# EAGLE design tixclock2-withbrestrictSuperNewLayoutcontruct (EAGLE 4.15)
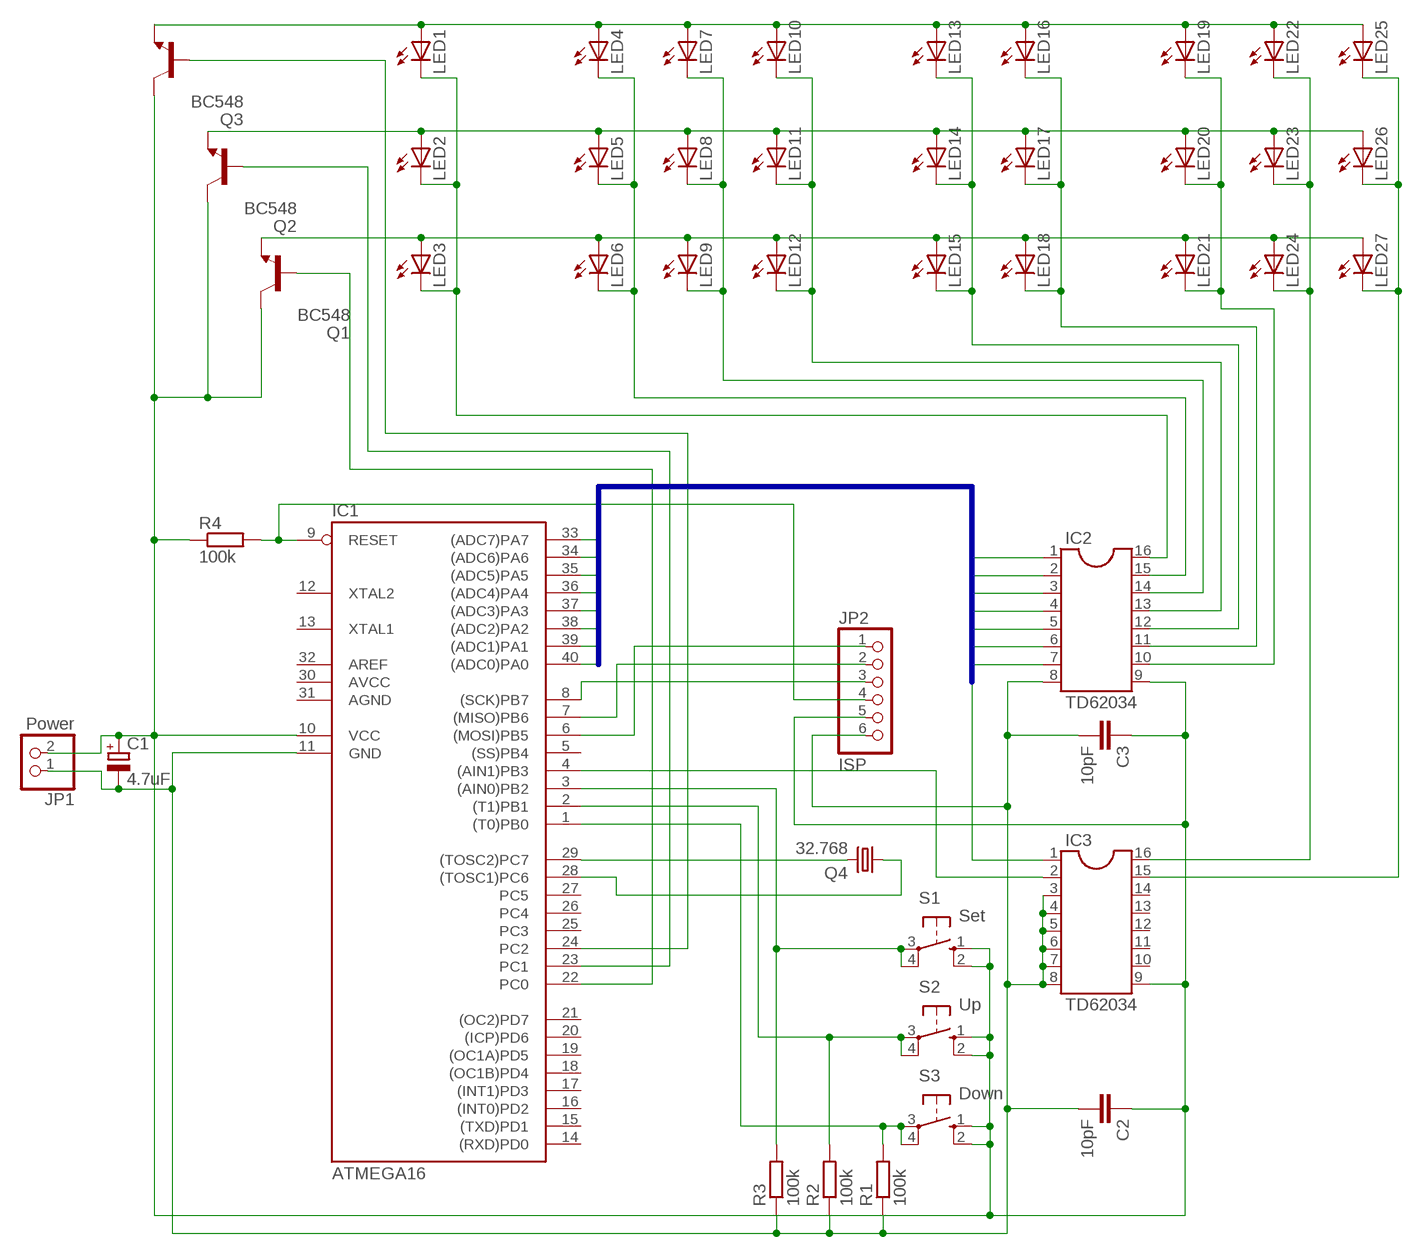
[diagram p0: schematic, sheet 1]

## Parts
C1  4.7uF  CPOL-EUE2.5-6  [E2,5-6]
C2  10pF  C-EU050-024X044  [C050-024X044]
C3  10pF  C-EU050-024X044  [C050-024X044]
IC1  ATMEGA16  AT90S8535P  [DIL40]
IC2  TD62034  DIL16  [DIL16]
IC3  TD62034  DIL16  [DIL16]
JP1  Power  PINHD-1X2  [1X02]
JP2  ISP  PINHD-1X6  [1X06]
LED1  LED5MM  [LED5MM]
LED2  LED5MM  [LED5MM]
LED3  LED5MM  [LED5MM]
LED4  LED5MM  [LED5MM]
LED5  LED5MM  [LED5MM]
LED6  LED5MM  [LED5MM]
LED7  LED5MM  [LED5MM]
LED8  LED5MM  [LED5MM]
LED9  LED5MM  [LED5MM]
LED10  LED5MM  [LED5MM]
LED11  LED5MM  [LED5MM]
LED12  LED5MM  [LED5MM]
LED13  LED5MM  [LED5MM]
LED14  LED5MM  [LED5MM]
LED15  LED5MM  [LED5MM]
LED16  LED5MM  [LED5MM]
LED17  LED5MM  [LED5MM]
LED18  LED5MM  [LED5MM]
LED19  LED5MM  [LED5MM]
LED20  LED5MM  [LED5MM]
LED21  LED5MM  [LED5MM]
LED22  LED5MM  [LED5MM]
LED23  LED5MM  [LED5MM]
LED24  LED5MM  [LED5MM]
LED25  LED5MM  [LED5MM]
LED26  LED5MM  [LED5MM]
LED27  LED5MM  [LED5MM]
Q1  BC548  [TO92-EBC]
Q2  BC548  [TO92-EBC]
Q3  BC548  [TO92-EBC]
Q4  32.768  CRYTALMM39SL  [MM39SL]
R1  100k  R-EU_0207/10  [0207/10]
R2  100k  R-EU_0207/10  [0207/10]
R3  100k  R-EU_0207/10  [0207/10]
R4  100k  R-EU_0207/10  [0207/10]
S1  Set  10-XX  [B3F-10XX]
S2  Up  10-XX  [B3F-10XX]
S3  Down  10-XX  [B3F-10XX]

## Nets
GND: C1.- C2.2 C3.2 IC1.11(GND) IC2.8 IC3.3 IC3.4 IC3.5 IC3.6 IC3.7 IC3.8 JP1.1 JP2.6 R1.1 R2.1 R3.1
N$1: IC1.4((AIN1)PB3) IC3.2
N$2: IC2.15 LED4.K(C) LED5.K(C) LED6.K(C)
N$3: IC1.9(RESET) JP2.4 R4.2
N$4: LED3.A LED6.A LED9.A LED12.A LED15.A LED18.A LED21.A LED24.A LED27.A Q1.E
N$5: LED2.A LED5.A LED8.A LED11.A LED14.A LED17.A LED20.A LED23.A LED26.A Q2.E
N$6: LED1.A LED4.A LED7.A LED10.A LED13.A LED16.A LED19.A LED22.A LED25.A Q3.E
N$7: IC2.16 LED1.K(C) LED2.K(C) LED3.K(C)
N$8: IC2.14 LED7.K(C) LED8.K(C) LED9.K(C)
N$9: IC2.13 LED10.K(C) LED11.K(C) LED12.K(C)
N$11: IC1.8((SCK)PB7) JP2.3
N$12: IC1.29((TOSC2)PC7) Q4.4
N$13: IC1.28((TOSC1)PC6) Q4.1
N$20: IC1.22(PC0) Q1.B
N$21: IC1.23(PC1) Q2.B
N$22: IC1.24(PC2) Q3.B
N$23: IC1.3((AIN0)PB2) R3.2 S1.3(P) S1.4(P1)
N$24: IC1.2((T1)PB1) R2.2 S2.3(P) S2.4(P1)
N$25: IC1.1((T0)PB0) R1.2 S3.3(P) S3.4(P1)
N$28: IC1.7((MISO)PB6) JP2.2
N$29: IC1.6((MOSI)PB5) JP2.1
N$32: IC2.12 LED13.K(C) LED14.K(C) LED15.K(C)
N$33: IC2.11 LED16.K(C) LED17.K(C) LED18.K(C)
N$34: IC2.10 LED19.K(C) LED20.K(C) LED21.K(C)
N$35: IC3.16 LED22.K(C) LED23.K(C) LED24.K(C)
N$36: IC3.15 LED25.K(C) LED26.K(C) LED27.K(C)
PA0: IC1.40((ADC0)PA0) IC2.1
PA1: IC1.39((ADC1)PA1) IC2.2
PA2: IC1.38((ADC2)PA2) IC2.3
PA3: IC1.37((ADC3)PA3) IC2.4
PA4: IC1.36((ADC4)PA4) IC2.5
PA5: IC1.35((ADC5)PA5) IC2.6
PA6: IC1.34((ADC6)PA6) IC2.7
PA7: IC1.33((ADC7)PA7) IC3.1
VCC: C1.+ C2.1 C3.1 IC1.10(VCC) IC2.9 IC3.9 JP1.2 JP2.5 Q1.C Q2.C Q3.C R4.1 S1.1(S) S1.2(S1) S2.1(S) S2.2(S1) S3.1(S) S3.2(S1)
Unconnected: IC1.5((SS)PB4) IC1.12(XTAL2) IC1.13(XTAL1) IC1.14((RXD)PD0) IC1.15((TXD)PD1) IC1.16((INT0)PD2) IC1.17((INT1)PD3) IC1.18((OC1B)PD4) IC1.19((OC1A)PD5) IC1.20((ICP)PD6) IC1.21((OC2)PD7) IC1.25(PC3) IC1.26(PC4) IC1.27(PC5) IC3.10 IC3.11 IC3.12 IC3.13 IC3.14

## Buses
PA[0..7]

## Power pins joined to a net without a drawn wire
AGND: IC1.31(AGND)
AREF: IC1.32(AREF)
AVCC: IC1.30(AVCC)

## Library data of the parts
C1 = rcl:CPOL-EU: POLARIZED CAPACITOR, European symbol
C2 C3 = rcl:C-EU: CAPACITOR, European symbol
IC1 = atmel:AT90*8535P: MICROCONTROLLER 8 Kbytes FLASH 512 bytes SRAM 512 bytes EEPROM UART 8-channel 10 bit ADC
IC2 IC3 = ic-package:DIL16: Dual In Line
JP1 = pinhead:PINHD-1X2: PIN HEADER
JP2 = pinhead:PINHD-1X6: PIN HEADER
LED1-LED27 = led:LED: LED
Q1-Q3 = transistor-npn:BC548*: NPN Transistor
Q4 = crystal:CRYTAL: CRYSTAL
R1-R4 = rcl:R-EU_: RESISTOR, European symbol
S1-S3 = switch-omron:10-XX: OMRON SWITCH

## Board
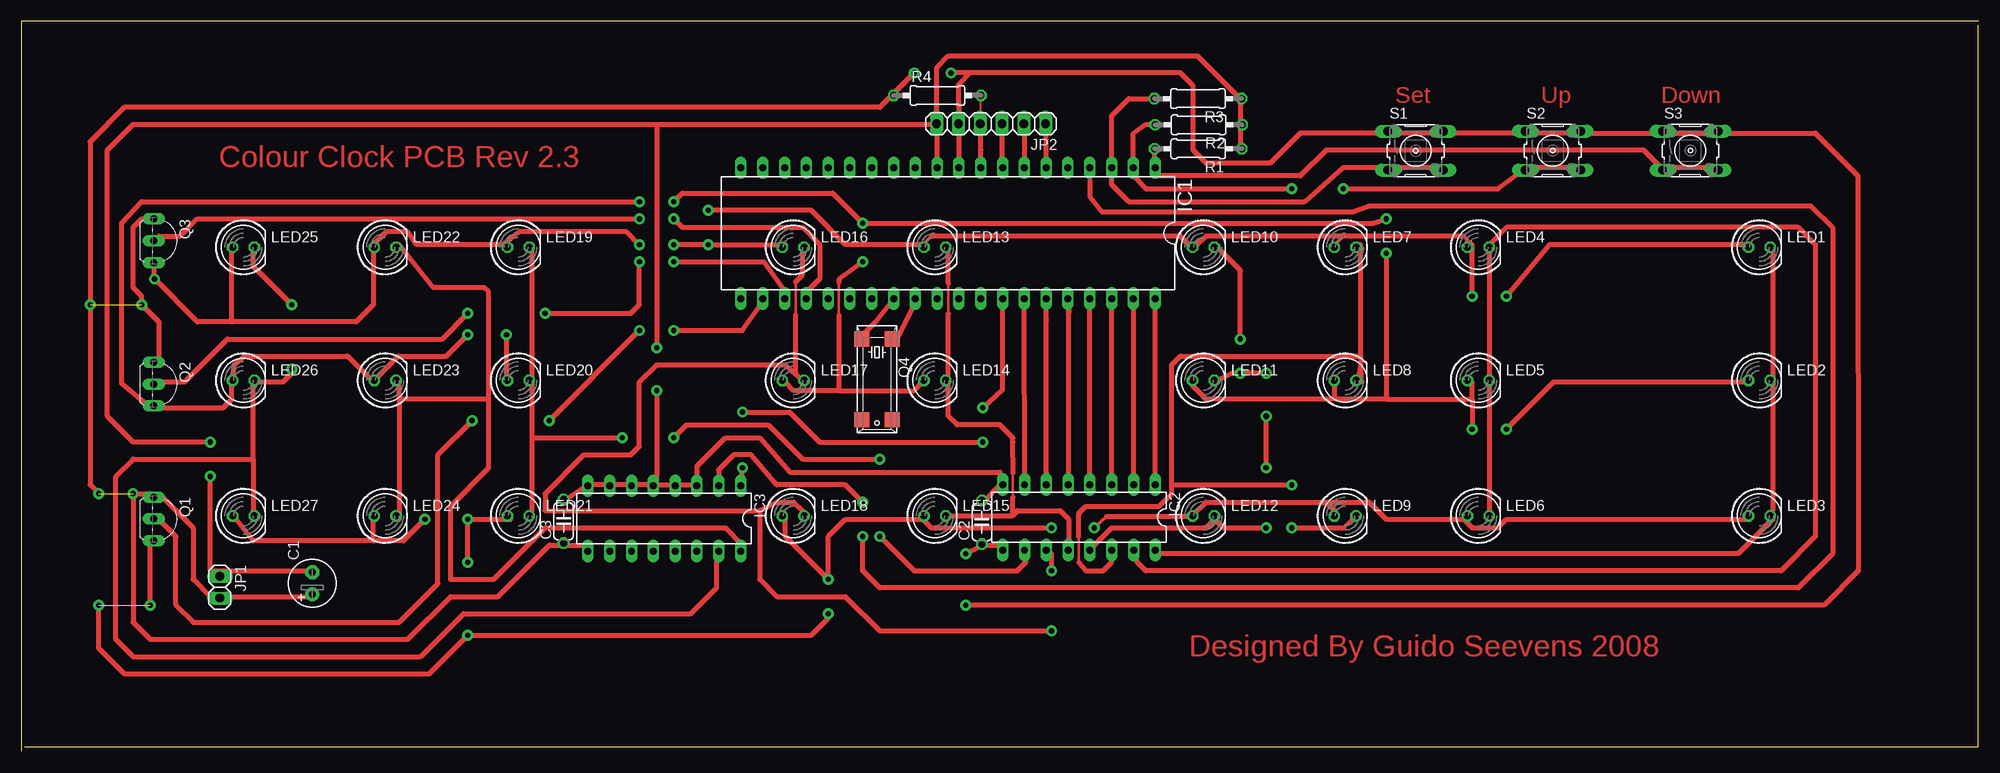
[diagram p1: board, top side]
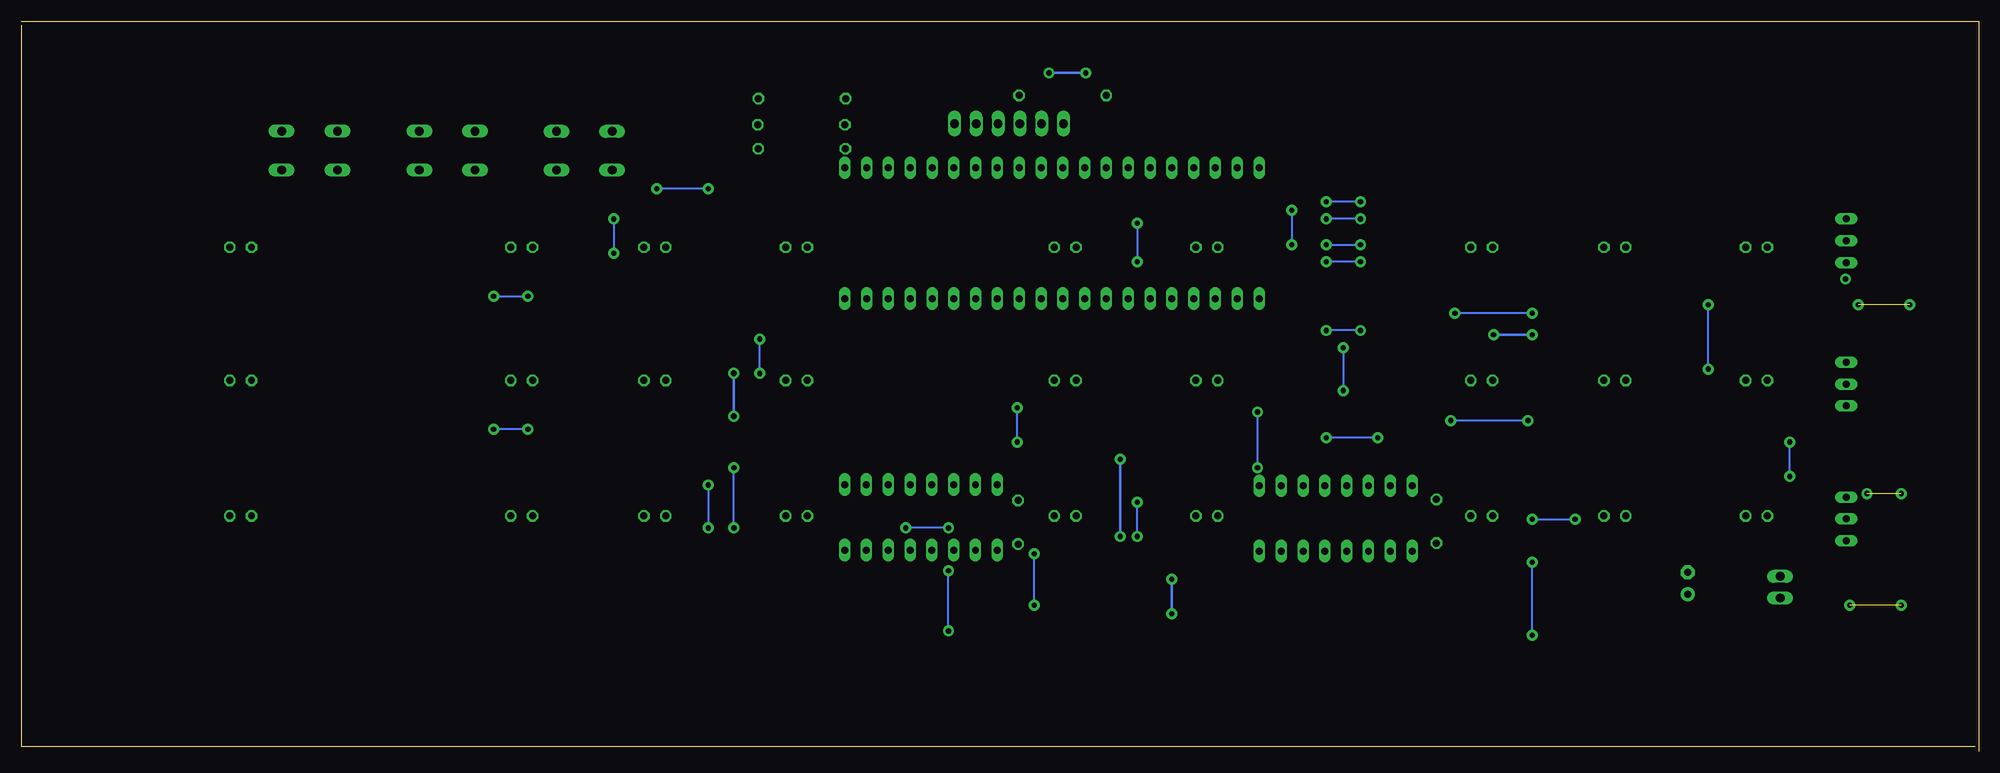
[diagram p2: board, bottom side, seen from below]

Size 228 x 85 mm. Coordinates in mm from the lower left corner, seen from the top.
Outline: 0.37,0.53 227.95,0.53 227.95,84.56
Outline: 228,85 0,85 0,0
Copper layers (1*16): Top 0.035mm / dielectric 1.5mm / Bottom 0.035mm
Design rules "default": minimum track width 10mil, minimum drill 24mil, track to track 8mil, track to pad 8mil, pad to pad 8mil, via to via 8mil, smd to smd 8mil, copper to edge 40mil, drill to drill 8mil, minimum pad ring 10mil, minimum via ring 8mil, stop-mask expansion 4mil, vias tented up to drill 0mil, thermal gap 10mil
bKeepout: area 22,54 to 30,63; area 38,54 to 46,63; area 54,54 to 62,63; area 54,39 to 62,48; area 38,39 to 46,48; area 22,39 to 30,48; area 22,23 to 30,32; area 38,23 to 46,32; area 54,23 to 62,32; area 86,54 to 94,63; area 102,54 to 110,63; area 134,54 to 142,63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
bRestrict: area 82,64 to 134,69; area 82,49 to 134,54; area 103,55 to 110,62; area 86,55 to 93,62; area 100,68 to 103,72; area 110,68 to 113,72; area 105,71 to 121,76; area 12,55 to 19,64; area 12,38 to 19,47; area 12,23 to 19,32; area 19,16 to 23,22; area 30,16 to 37,23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

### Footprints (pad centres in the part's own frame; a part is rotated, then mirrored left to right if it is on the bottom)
E2,5-6 = drill 0.813 pad 1.6 round: + -1.27,0 | drill 0.813 pad 1.6 octagon: - 1.27,0
C050-024X044 = drill 0.813 octagon: 1 -2.54,0; 2 2.54,0
DIL40 = drill 0.813 long: 1 -24.13,-7.62; 2 -21.59,-7.62; 3 -19.05,-7.62; 4 -16.51,-7.62; 5 -13.97,-7.62; 6 -11.43,-7.62; 7 -8.89,-7.62; 8 -6.35,-7.62; 9 -3.81,-7.62; 10 -1.27,-7.62; 11 1.27,-7.62; 12 3.81,-7.62; 13 6.35,-7.62; 14 8.89,-7.62; 15 11.43,-7.62; 16 13.97,-7.62; 17 16.51,-7.62; 18 19.05,-7.62; 19 21.59,-7.62; 20 24.13,-7.62; 21 24.13,7.62; 22 21.59,7.62; 23 19.05,7.62; 24 16.51,7.62; 25 13.97,7.62; 26 11.43,7.62; 27 8.89,7.62; 28 6.35,7.62; 29 3.81,7.62; 30 1.27,7.62; 31 -1.27,7.62; 32 -3.81,7.62; 33 -6.35,7.62; 34 -8.89,7.62; 35 -11.43,7.62; 36 -13.97,7.62; 37 -16.51,7.62; 38 -19.05,7.62; 39 -21.59,7.62; 40 -24.13,7.62
DIL16 = drill 0.813 long: 1 -8.89,-3.81; 2 -6.35,-3.81; 3 -3.81,-3.81; 4 -1.27,-3.81; 5 1.27,-3.81; 6 3.81,-3.81; 7 6.35,-3.81; 8 8.89,-3.81; 9 8.89,3.81; 10 6.35,3.81; 11 3.81,3.81; 12 1.27,3.81; 13 -1.27,3.81; 14 -3.81,3.81; 15 -6.35,3.81; 16 -8.89,3.81
1X02 = drill 1.016 long: 1 -1.27,0; 2 1.27,0
1X06 = drill 1.016 long: 1 -6.35,0; 2 -3.81,0; 3 -1.27,0; 4 1.27,0; 5 3.81,0; 6 6.35,0
LED5MM = drill 0.813 octagon: A -1.27,0; K 1.27,0
TO92-EBC = drill 0.813 long: B 0,-1.27; C -2.54,-1.27; E 2.54,-1.27
MM39SL = smd 1.778 x 1.778: 1 -4.699,-1.778; 2 4.699,-1.778; 3 4.699,1.778; 4 -4.699,1.778
0207/10 = drill 0.813 octagon: 1 -5.08,0; 2 5.08,0
B3F-10XX = drill 1.016 long: 1 -3.251,2.261; 2 3.251,2.261; 3 -3.251,-2.261; 4 3.251,-2.261

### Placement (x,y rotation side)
C1  33.89,19.55 90 top
C2  111.89,26.66 90 top
C3  63.16,26.77 90 top
IC1  107.95,60.33 180 top
IC2  123.21,27.23 180 top
IC3  74.88,27.1 180 top
JP1  23.11,19.09 270 top
JP2  112.96,73.09 180 top
LED1  202.47,58.69 0 top
LED2  202.47,43.18 0 top
LED3  202.47,27.4 0 top
LED4  169.72,58.69 0 top
LED5  169.72,43.18 0 top
LED6  169.72,27.4 0 top
LED7  154.21,58.69 0 top
LED8  154.21,43.18 0 top
LED9  154.21,27.4 0 top
LED10  137.7,58.69 0 top
LED11  137.7,43.18 0 top
LED12  137.7,27.4 0 top
LED13  106.41,58.69 0 top
LED14  106.41,43.18 0 top
LED15  106.41,27.4 0 top
LED16  89.9,58.69 0 top
LED17  89.9,43.18 0 top
LED18  89.9,27.4 0 top
LED19  57.88,58.69 0 top
LED20  57.88,43.18 0 top
LED21  57.88,27.4 0 top
LED22  42.37,58.69 0 top
LED23  42.37,43.18 0 top
LED24  42.37,27.4 0 top
LED25  25.86,58.69 0 top
LED26  25.86,43.18 0 top
LED27  25.86,27.4 0 top
Q1  16.68,27.05 270 top
Q2  16.68,42.75 270 top
Q3  16.68,59.45 270 top
Q4  99.68,43.31 270 top
R1  137.09,70.17 180 top
R2  137.14,72.96 180 top
R3  137.06,76.01 180 top
R4  106.7,76.38 0 top
S1  162.43,69.95 0 top
S2  178.4,69.95 0 top
S3  194.43,69.95 0 top

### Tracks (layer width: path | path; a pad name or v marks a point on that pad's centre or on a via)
GND  (via drill 0.61 pad 1.27)
  Top 0.254: 69,31 IC3.7 68,31 | 63,29 C3.2 | 66,31 IC3.8 | 114,31 IC2.8 | 74,31 IC3.5 73,31 | 79,31 IC3.3 | 76,31 IC3.4 | 112,29 C2.2 | 71,31 IC3.6 | 34,21 C1.- | 106.62,67.5 IC1.11 | 142,73 R2.1 | 142,76 R3.1
  Top 0.61: 69,31 71,31 73,31 | 63,29 66,31 68,31 | 74,31 76,31 79,31 | 112,29 114,31 114,32.5 89.5,32.5 86,36.5 82,36.5 78.73,33.23 IC3.3 | 22,21 34,21 | 106.62,67.5 106.64,73.38 JP2.6 | R1.1 142,71 142,73 142,76 137,81 108,81 106.63,79.61 JP2.6 | 22,21 v22,32 | v22,36 13,36 10,39 10,70 13,73 74,73 | 74,73 106,73 JP2.6 | 22,21 JP1.1 | v74,42 74,32 IC3.5 | 74,73 v74,47
  Bottom 0.254: v22,32 v22,36 | v74,47 v74,42
N$1  (via drill 0.61 pad 1.27)
  Top 0.254: 124.49,66.43 IC1.4
  Top 0.61: v98,29 96,31 88,31 85,34.5 83,34.5 81.23,32.76 IC3.2 | v98,25 98,21 100,19 207,19 211,23 211,61 208.5,63.5 157,63.5 155.04,62.79 125.9,62.79 124.49,64.53 124.49,66.43
  Bottom 0.254: v98,25 v98,29
N$2
  Top 0.254: 171,28 LED6.K | 171,43 LED5.K | 171,59 LED4.K
  Top 0.61: 171,28 171,43 171,59 173,61 207,61 209,59 209,25 205,21 131,21 130,22 IC2.15
N$3
  Top 0.254: 111.76,73.5 JP2.4 | IC1.9 111.76,67.07 | 111.76,70.05 R4.2
  Top 0.61: 111.76,73.5 111.76,70.05 111.76,67.07
N$4  (via drill 0.6 pad 1.27, 0.61, 0.61 pad 1.27)  (1 unrouted)
  Top 0.254: 153,28 LED9.A | 201,27 LED3.A | 168,27 LED6.A | 25,27 LED27.A | 41,27 LED24.A | 57,27 LED21.A | 89,27 LED18.A | 136.25,27.33 LED12.A
  Top 0.406: 15,24 Q1.E | v124.98,26 126.41,27.33 | 105,27 LED15.A
  Top 0.61: 152,29 138,29 136.25,27.33 126.41,27.33 | 152,29 153,28 | 152,29 157,29 159,27 168,27 169,26 172,26 173,27 201,27 | 25,27 27,24.5 41,24.5 | 41,24.5 41,27 | 57,27 v52,27 v52,22 | v47,27 44.5,24.5 41,24.5 | v15,17 15,24 | v9,17 9,12 12,9 47.5,9 v52,13.5 92,13.5 94,15.5 v94,16 | 89,27 89,25 v94,20 94,25 96,27 105,27 106,26 v120,26
  Bottom 0.254: v52,27 v47,27 | v52,13.5 v52,22 | v120,26 v124.98,26
  Bottom 0.305: v94,16 v94,20
N$5  (via drill 0.6 pad 1.27, 0.61 pad 1.27)
  Top 0.254: 136.5,42.5 LED11.A | 153,43 LED8.A | 169,43 LED5.A | 201,43 LED2.A | 89,43 LED17.A | 105,43 LED14.A | 56.5,43 LED20.A | 41,43 LED23.A
  Top 0.305: 95.23,54.58 95.23,50.8 | LED26.A 24.5,43.09
  Top 0.406: 24.5,43 LED26.A | 25.83,45.9 26,46
  Top 0.61: 136.5,42.5 138,41 153,41 | 153,41 153,43 | 159,41 169,41 | 169,41 169,43 | 159,41 153,41 | 201,43 178.5,43 v173,37.5 | 169,41 v169,37.5 | 89,43 90,42 95.24,42 | 95.24,42 104,42 105,43 | 25.83,45.9 24.83,45.07 24.5,43 | 41,43 38,46 26,46 | 95.23,54.58 95.24,54.97 v98,57 | 95.23,50.8 95.24,42 | v76,64 77,65 94.5,65 v98,61.5 157.5,61.5 v159,62 | v72,64 14,64 11.66,61.51 11.66,42.8 15,40 Q2.E 15.62,40 23.5,40 24.5,41 24.5,43 | v159,58 159,41 | LED23.A 43.92,46 49.5,46 v52,48.5 | LED20.A 56.5,43.07 56.5,43 v56.5,48.5 | 24.5,43 24.5,43.09
  Bottom 0.254: v169,37.5 v173,37.5 | v98,61.5 v98,57 | v72,64 v76,64 | v159,62 v159,58
  Bottom 0.305: v52,48.5 v56.5,48.5
N$6  (via drill 0.61 pad 1.27)
  Top 0.254: 41,59 LED22.A | 89,59 LED16.A | 56,59 LED19.A | 136,59 LED10.A 137,59 | 153,59 LED7.A | 169,59 LED4.A | LED1.A 201,59 | 105,59 LED13.A
  Top 0.406: 106,60 105,59 | 154,60 153,59 | 169,59 168,60
  Top 0.61: 24.5,50 39,50 41,52 41,59 42.5,60.5 45,60.5 46,59 56,59 58,60.5 70.5,60.5 v72,59 | v76,59 v80,59 89,59 | 106,60 135,60 136,59 | 168,60 154,60 138,60 137,59 | 201,59 178,59 v173,53 | v169,53 169,59 | v80,63 92,63 96,59 105,59 | Q3.E v15.5,55 20.5,50 24.5,50 | LED25.A 24.5,58.6 24.5,50
  Bottom 0.254: v76,59 v72,59 | v173,53 v169,53 | v80,63 v80,59
N$7
  Top 0.254: 132,23 IC2.16 | 204,27 LED3.K 204,28 | LED1.K 204,59 | 204,43 LED2.K
  Top 0.61: 132,23 200,23 204,27 | 204,28 204,43 204,59
N$8  (via drill 0.61 pad 1.27)
  Top 0.254: 156,46 LED8.K 156,43 | 155,27 LED9.K | 156,59 LED7.K
  Top 0.305: 123.2,21.95 123.17,24.97
  Top 0.406: 123.2,27.58 123.18,27.68 | 154,26 155,27
  Top 0.61: 123.2,21.95 124,21 126,21 127,22 IC2.14 | 123.17,24.97 123.2,27.58 | 123.18,27.68 124,28.5 132.5,28.5 134,30 134,31 | 156,46 135,46 134,45 134,31 | v148,26 154,26 | 134,31 v148,31 | 156,46 156,43 | 156,46 156,59
  Bottom 0.254: v148,31 v148,26
N$9  (via drill 0.61 pad 1.27, 0.7 pad 1.27)
  Top 0.254: 139,59 LED10.K | 139,43 LED11.K | 139,27 LED12.K
  Top 0.61: 139,43 141,44 v142,44 v145,44 | v142,48 142,56 139,59 | IC2.13 125,24 127,26 138,26 139,27 140,26 v145,26 | v145,33 v145,39
  Bottom 0.254: v142,44 v142,48 | v145,26 v145,33
  Bottom 0.305: v145,39 v145,44
N$11
  Top 0.254: 114.28,67 IC1.8 | 114.28,73.43 JP2.3
  Top 0.61: 114.28,67 114.28,73.43
N$12
  Top 0.254: 102,48 101,48 Q4.4
  Top 0.61: 102,48 104,52 IC1.29
N$13
  Top 0.254: Q4.1 97.5,48 | 101.5,52.5 IC1.28
  Top 0.61: 97.5,48 99.5,50 101.5,52.5
N$20  (via drill 0.61 pad 1.27)
  Top 0.254: 86.5,52.5 IC1.22
  Top 0.406: 16,27 Q1.B
  Top 0.61: 16,27 18,25 18,17 20,15 44,15 48.5,19.5 48.5,34.5 v52.5,38.5 | v61.5,38.5 v72,49 | v76,49 84,49 86.5,52.5
  Bottom 0.254: v52.5,38.5 v61.5,38.5 | v72,49 v76,49
N$21  (via drill 0.61 pad 1.27)
  Top 0.254: 89,53.5 IC1.23
  Top 0.406: Q2.B 16,43
  Top 0.61: 16,43 19,43 24,48 49,48 v52,51 | v72,57 72,52 71,51 v61,51 | v76,57 86.5,57 89,53.5
  Bottom 0.254: v52,51 v61,51 | v72,57 v76,57
N$22  (via drill 0.61 pad 1.27)
  Top 0.254: 91.5,53.5 IC1.24
  Top 0.406: Q3.B 16,60
  Top 0.61: 91.5,53.5 93,55 93,59 91,61 77,61 v76,62 | v72,62 20.5,62 18.5,60 16,60
  Bottom 0.254: v72,62 v76,62
N$23
  Top 0.254: 127,67 IC1.3
  Top 0.406: 160,68 S1.3 158,68 | 165,68 S1.4
  Top 0.61: 160,68 165,68 | IC1.3 127,74 129,76 R3.2 | 158,68 154,68 149.5,64 129,64 127,66 127,67
N$24  (via drill 0.61 pad 1.27)
  Top 0.254: 129.55,67.02 IC1.2 129.5,67.5
  Top 0.406: 176,68 S2.3 174,67 | 181,68 S2.4 | 129.5,67.5 129.5,67
  Top 0.61: 129.55,67.02 129.5,71 129.55,71.95 131,73 132.02,73 R2.2 | 176,68 181,68 | 129.5,67 131,65.5 v148,65.5 | v154,65.5 172,65.5 174,67
  Bottom 0.254: v148,65.5 v154,65.5
N$25
  Top 0.254: 132,70 R1.2 | 132,67.5 IC1.1
  Top 0.305: S3.3 191,68
  Top 0.406: S3.3 192,68 | 197,68 S3.4 | 132,67 IC1.1
  Top 0.61: 132,70 132,67.5 132,67 149,67 152,70 189,70 191,68 | 192,68 197,68
N$28
  Top 0.254: IC1.7 116.86,67.02 | 116.86,73.45 JP2.2
  Top 0.61: 116.86,67.02 116.86,73.45
N$29
  Top 0.254: IC1.6 119.38,67.36 | 119.38,73.59 JP2.1
  Top 0.61: 119.38,67.36 119.38,73.59
N$32
  Top 0.254: 108,58.5 LED13.K | 122,24 IC2.12 | 108,43 LED14.K
  Top 0.305: 108,51 108,54.5 | 115.51,29.58 115.51,32.28
  Top 0.406: 116,27.91 116,28 | 115.51,32.28 115.52,32.39
  Top 0.61: 108,51 108,43 108,39 109,38 114,38 115.51,36.49 115.51,36.01 115.52,32.39 | 108,54.5 108,58.5 | 115.51,27.42 116,27.91 | 116,28 121,28 122,27 122,24 | 115.51,27.42 108.85,27.42 LED15.K | 115.51,27.42 115.51,29.58
N$33  (via drill 0.61 pad 1.27)
  Top 0.254: 91,28 LED18.K | 91,43 LED17.K | 91,59 LED16.K
  Top 0.305: 90.2,50.82 90.2,54.66
  Top 0.406: 120,23 IC2.11
  Top 0.61: 91,28 90,29 88,29 86,28 | 86,28 61,28 61,30 65.5,34.5 71,34.5 72,35.5 72,43 74,45 89,45 90.2,43.9 | 90.2,43.9 91,43 | v120,21 120,23 | v120,14 100,14 96,18 88,18 86,20 86,28 | 91,59 91,55.5 90.2,54.66 | 90.2,43.9 90.2,50.82
  Bottom 0.254: v120,14 v120,21
N$34  (via drill 0.6 pad 1.27, 0.61 pad 1.27)
  Top 0.254: 59.5,59 LED19.K | 59.5,43 LED20.K
  Top 0.406: LED21.K 59.5,28 | 117,22 117,24
  Top 0.61: 59.5,36.5 59.5,43 59.5,59 | 59.5,28 59.5,36.5 | v76,36.5 77.5,38 87,38 91,34 v100,34 | 59.5,36.5 v70,36.5 | v100,25 104,21 116,21 117,22 | IC2.10 116.86,23.14 arc90 117,23 117,24
  Bottom 0.254: v70,36.5 v76,36.5
  Bottom 0.305: v100,34 v100,25
N$35
  Top 0.254: 44,59 LED22.K | 84,24 IC3.16 | 44,43 LED23.K
  Top 0.406: 44,27 LED24.K
  Top 0.61: 44,41 44,27 | 54.42,41 44,41 | 44,59 48,54 53.92,54 54.42,53.5 54.42,41 | 84,24 82,26 61,26 55,20 49.99,20 50,28.5 54.42,33 54.42,41 | 44,41 44,43
N$36  (via drill 0.61 pad 1.27)
  Top 0.254: 27,28 LED27.K | 27,43 LED26.K | 27,59 LED25.K | 81,22 IC3.15
  Top 0.61: 27,34 27,28 | v31.5,52 27,56.5 27,59 | v31.5,44.5 31.5,44 30.5,43 27,43 27,34 | 81,22 81,19 78,16 51.5,16 46.5,11 13,11 11,13 11,32 13,34 27,34
  Bottom 0.254: v31.5,44.5 v31.5,52
PA0
  Top 0.305: 132.08,52 IC1.40
  Top 0.61: IC2.1 132.08,52
PA1
  Top 0.305: 129.56,52.26 129.5,52 129.5,52.5 IC1.39
  Top 0.61: IC2.2 129.56,52.26
PA2
  Top 0.305: 127,52.5 IC1.38
  Top 0.61: IC2.3 127,52.5
PA3
  Top 0.254: 124.67,52.46 124.5,52
  Top 0.305: 124.45,52.35 124.67,52.46
  Top 0.61: 124.67,52.46 IC1.37 | IC2.4 124.45,52.35
PA4
  Top 0.254: 122,51.5 IC1.36
  Top 0.61: 122,51 122,51.5 122,32 IC2.5
PA5
  Top 0.61: IC2.6 119.39,32.39 119.39,50.2 IC1.35
PA6
  Top 0.305: 116.83,52.09 IC1.34
  Top 0.61: IC2.7 116.83,52.09
PA7  (via drill 0.61 pad 1.27)
  Top 0.254: IC3.1 84,31
  Top 0.61: 84,31 v84,33 | v84,39.5 89.5,39.5 93,36 v112,36 | v112,40 114.32,42.14 114.32,50 IC1.33
  Bottom 0.254: v84,33 v84,39.5 | v112,36 v112,40
VCC  (via drill 0.6 pad 1.27, 0.61 pad 1.27)  (2 unrouted)
  Top 0.254: 66,24 IC3.9 | 34,18 C1.+ | 63,24 C3.1 | IC1.10 109,67 | 112,24 C2.1
  Top 0.305: S1.1 159,72
  Top 0.406: 15,30 Q1.C | 16,45 Q2.C | 14,62 Q3.C | S3.2 198,72
  Top 0.61: 66,24 63,24 61.5,24 55.5,18 50,18 45,13 15,13 13,15 v13,30 15,30 | 22,18 20,20 20,26 16.5,29.5 15.5,29.5 Q1.C | 22,18 34,18 | 22,18 JP1.2 | 16,45 16,50 v14,52 14,53 13,54 13,61 14,62 | IC1.10 109.19,67.07 109.19,73 JP2.5 109.2,75.64 109.16,75.16 109.16,77.64 110.5,79 | S3.2 197,72 192,72 S3.1 190,72 183,72 S2.2 181,72 176,72 S2.1 174,72 167,72 S1.2 165,72 160,72 S1.1 | IC2.9 114,24 112,24 v110,23 | v110,17 210,17 214,21 213.95,67 209,72 198,72 | 110.5,79 135,79 136.5,77.5 136.5,70 138,68.5 145.5,68.5 149,72 159,72 | v9,30 8,31 v8,52 8,71 12,75 100,75 101.5,76.5 | v104,79 101.5,76.5 | 110.5,79 v108.29,79 | 101.5,76.5 R4.1
  Bottom 0.254: v110,17 v110,23
  Bottom 0.305: v108.29,79 v104,79

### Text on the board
Top: Set | Up | Down | Colour Clock PCB Rev 2.3 | Designed By Guido Seevens 2008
